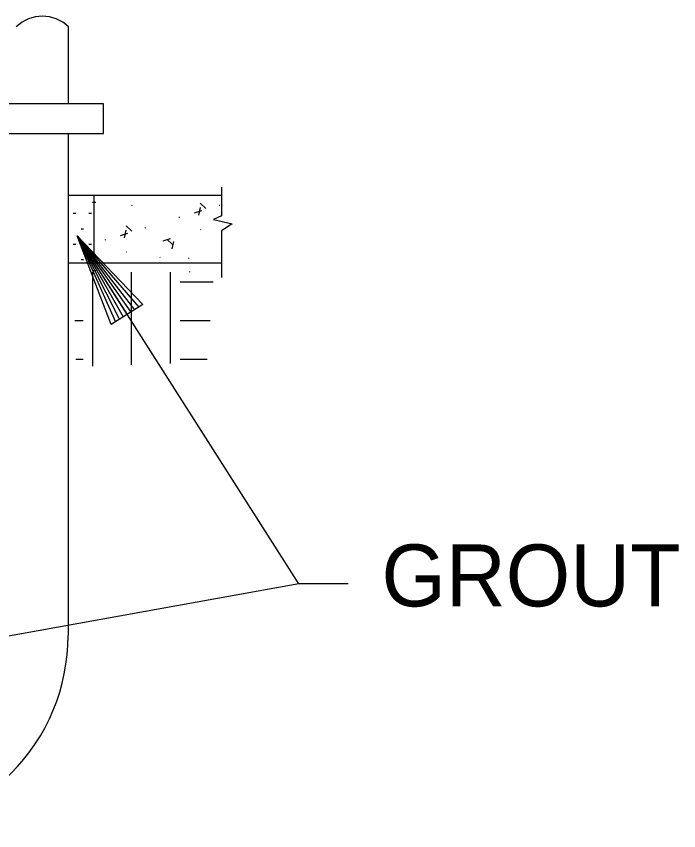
# Model space of a CAD drawing. Extents: x 10040.55 to 10045.84, y 10033.26 to 10035.76.
# Drawn here: x 10041.5052 to 10041.6121, y 10033.8193 to 10033.9508 of the extents above; entities that cross this region are included whole.
import ezdxf

# ---------------------------------------------------------------- set-up
doc = ezdxf.new("R2010")
doc.units = 0
doc.layers.add('Level 2', color=7, linetype='Continuous')

msp = doc.modelspace()

# ---------------------------------------------------------------- linework, layer by layer
at = {"layer": 'Level 2'}
for p, q in [((10041.51357, 10033.94913), (10041.51357, 10033.93668)), ((10041.51357, 10033.93191), (10041.51357, 10033.85089)), ((10041.53835, 10033.92324), (10041.53835, 10033.91863)), ((10041.5136, 10033.92197), (10041.53833, 10033.92197)), ((10041.51772, 10033.92197), (10041.51772, 10033.911)), ((10041.51805, 10033.92076), (10041.51751, 10033.92076)), ((10041.52384, 10033.92034), (10041.52382, 10033.92024)), ((10041.53582, 10033.91981), (10041.53491, 10033.92067)), ((10041.53797, 10033.92033), (10041.53808, 10033.92036)), ((10041.51441, 10033.91904), (10041.51482, 10033.91904)), ((10041.51691, 10033.91904), (10041.51732, 10033.91904)), ((10041.53398, 10033.91911), (10041.53518, 10033.91948)), ((10041.53488, 10033.91994), (10041.53459, 10033.91872)), ((10041.53154, 10033.91835), (10041.53156, 10033.91845)), ((10041.53835, 10033.91863), (10041.53705, 10033.91802)), ((10041.53705, 10033.91802), (10041.54006, 10033.91731)), ((10041.51566, 10033.91654), (10041.51607, 10033.91654)), ((10041.52291, 10033.91628), (10041.52263, 10033.91506)), ((10041.52386, 10033.91615), (10041.52295, 10033.917)), ((10041.52601, 10033.91668), (10041.52614, 10033.91671)), ((10041.53502, 10033.91641), (10041.53493, 10033.91638)), ((10041.54006, 10033.91731), (10041.53835, 10033.91621)), ((10041.52313, 10033.90269), (10041.51501, 10033.91539)), ((10041.52054, 10033.90107), (10041.51501, 10033.91539)), ((10041.52564, 10033.9043), (10041.51501, 10033.91539)), ((10041.51501, 10033.91539), (10041.52185, 10033.90189)), ((10041.51501, 10033.91539), (10041.52428, 10033.90342)), ((10041.51501, 10033.91539), (10041.52124, 10033.9015)), ((10041.51501, 10033.91539), (10041.52248, 10033.90229)), ((10041.51501, 10033.91539), (10041.52371, 10033.90307)), ((10041.51501, 10033.91539), (10041.52499, 10033.90389)), ((10041.52203, 10033.91546), (10041.52322, 10033.91582)), ((10041.53835, 10033.91621), (10041.53835, 10033.90868)), ((10041.51441, 10033.91404), (10041.51482, 10033.91404)), ((10041.51691, 10033.91404), (10041.51732, 10033.91404)), ((10041.51958, 10033.9147), (10041.5196, 10033.9148)), ((10041.53004, 10033.91489), (10041.52884, 10033.91452)), ((10041.52949, 10033.91485), (10041.53041, 10033.914)), ((10041.53038, 10033.91328), (10041.53066, 10033.91449)), ((10041.52307, 10033.91276), (10041.52297, 10033.91273)), ((10041.53833, 10033.91099), (10041.5136, 10033.91099)), ((10041.51566, 10033.91154), (10041.51607, 10033.91154)), ((10041.52844, 10033.91189), (10041.52836, 10033.91196)), ((10041.533, 10033.91181), (10041.53298, 10033.91171)), ((10041.51751, 10033.90979), (10041.51805, 10033.90979)), ((10041.51757, 10033.89432), (10041.51757, 10033.90954)), ((10041.52382, 10033.89455), (10041.52382, 10033.90954)), ((10041.53008, 10033.89478), (10041.53008, 10033.90954)), ((10041.5332, 10033.90954), (10041.5332, 10033.90965)), ((10041.53164, 10033.90798), (10041.537, 10033.90798)), ((10041.52564, 10033.9043), (10041.52054, 10033.90107)), ((10041.51468, 10033.90173), (10041.51601, 10033.90173)), ((10041.53164, 10033.90173), (10041.53651, 10033.90173)), ((10041.51483, 10033.89548), (10041.51601, 10033.89548)), ((10041.53164, 10033.89548), (10041.53601, 10033.89548)), ((10041.55081, 10033.85919), (10041.4429, 10033.83979))]:
    msp.add_line(p, q, dxfattribs=at)
msp.add_lwpolyline([(10041.49119, 10033.93668), (10041.49119, 10033.93191), (10041.51927, 10033.93191), (10041.51927, 10033.93668)], close=True, dxfattribs=at)
msp.add_lwpolyline([(10041.55877, 10033.85919), (10041.55081, 10033.85919), (10041.51501, 10033.91539)], dxfattribs=at)
for centre, radius, start, end in [((10041.50942, 10033.94476), 0.00607, 45.9788, 134.0225), ((10041.48203, 10033.85088), 0.03154, 269.9817, 0)]:
    msp.add_arc(centre, radius, start, end, dxfattribs=at)

# ---------------------------------------------------------------- texts
msp.add_text('GROUT', height=0.01, dxfattribs=at).set_placement((10041.56416, 10033.85556))

doc.saveas('drawing.dxf')
